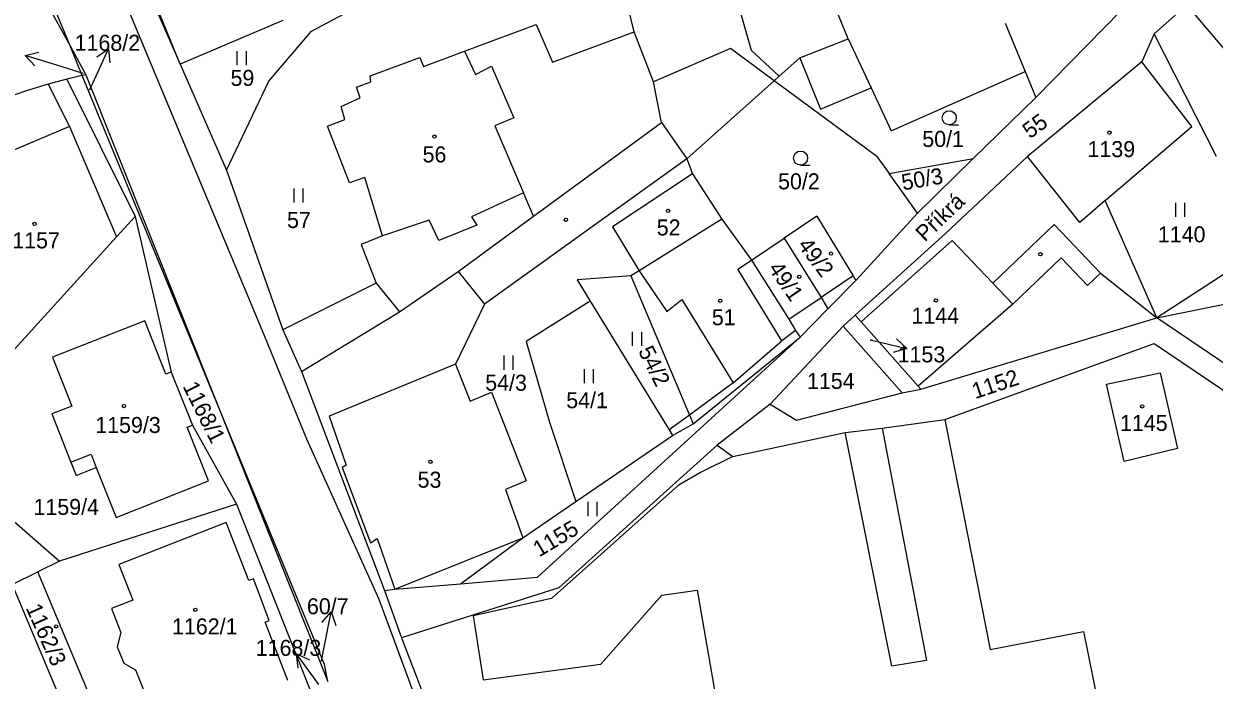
# Model space of a CAD drawing. Extents: x -670359 to -668019, y -978807 to -976674.
# Drawn here: x -670231.3 to -670104.9, y -977870.8 to -977801.1 of the extents above; entities that cross this region are included whole.
import ezdxf

# ---------------------------------------------------------------- set-up
doc = ezdxf.new("R2010")
doc.units = 0
for name, color, linetype in [('Hranice parcel', 7, 'Continuous'), ('Parcelní čísla', 7, 'Continuous'), ('Pop  PČ popisy', 7, 'Continuous'), ('Vnitřní kresba', 7, 'Continuous'), ('Značky budov', 7, 'Continuous'), ('Značky kultur', 7, 'Continuous')]:
    doc.layers.add(name, color=color, linetype=linetype)

msp = doc.modelspace()

# ---------------------------------------------------------------- linework, layer by layer
at = {"layer": 'Hranice parcel'}
for points in [[(-670183.39, -977889.81), (-670193.56, -977862.25), (-670201.26, -977845.22), (-670205.62, -977834.5), (-670231.98, -977771.32), (-670242.71, -977745.05), (-670249.53, -977728.04), (-670253.85, -977714.41), (-670254.54, -977710.9), (-670255.07, -977705.75), (-670255.17, -977699.87), (-670254.7, -977694.67), (-670252.82, -977684.15), (-670242.83, -977643.13)], [(-670241.06, -977776.57), (-670231.37, -977794.32), (-670228.95, -977798.75), (-670226.38, -977803.45)], [(-670160.77, -977780.44), (-670154.08, -977803.89)], [(-670224.46, -977783.08), (-670214.71, -977805.39)], [(-670166.5, -977801.96), (-670170.62, -977785.06)], [(-670143.78, -977802.68), (-670145.82, -977797.63)], [(-670226.38, -977803.45), (-670228.39, -977798.54)], [(-670200.75, -977801.88), (-670196.17, -977799.43)], [(-670123.86, -977808.92), (-670114.79, -977799.68)], [(-670107.82, -977799.09), (-670111.29, -977802.18)], [(-670203.78, -977800.74), (-670214.71, -977805.39)], [(-670184.52, -977803.99), (-670176.9, -977801.17)], [(-670176.9, -977801.17), (-670175.17, -977805.18)], [(-670205.27, -977807.21), (-670200.75, -977801.88)], [(-670175.17, -977805.18), (-670166.5, -977801.96)], [(-670164.46, -977807.25), (-670166.5, -977801.96)], [(-670148.92, -977804.72), (-670143.78, -977802.68)], [(-670111.29, -977802.18), (-670112.59, -977805.14)], [(-670104.66, -977815.19), (-670111.29, -977802.18)], [(-670226.38, -977803.45), (-670224.71, -977806.51)], [(-670225.09, -977806.6), (-670226.38, -977803.45)], [(-670188.86, -977805.64), (-670184.52, -977803.99)], [(-670154.08, -977803.89), (-670151.09, -977806.66)], [(-670214.71, -977805.39), (-670209.78, -977816.65)], [(-670194.54, -977806.64), (-670189.25, -977804.68)], [(-670189.25, -977804.68), (-670188.86, -977805.64)], [(-670148.92, -977804.72), (-670151.09, -977806.66)], [(-670148.92, -977804.72), (-670146.72, -977810.18)], [(-670112.59, -977805.14), (-670124.75, -977815.21)], [(-670107.3, -977812.02), (-670112.59, -977805.14)], [(-670225.09, -977806.6), (-670226.72, -977806.98)], [(-670224.71, -977806.51), (-670225.09, -977806.6)], [(-670211.12, -977840.59), (-670225.09, -977806.6)], [(-670224.71, -977806.51), (-670211.12, -977840.59)], [(-670194.47, -977807.28), (-670194.54, -977806.64)], [(-670151.63, -977807.14), (-670151.09, -977806.66)], [(-670139.21, -977812.47), (-670125, -977806.17)], [(-670125, -977806.17), (-670123.86, -977808.92)], [(-670228.72, -977807.52), (-670230.81, -977808.15)], [(-670226.72, -977806.98), (-670228.72, -977807.52)], [(-670228.72, -977807.52), (-670226.43, -977812.02)], [(-670226.72, -977806.98), (-670219.46, -977821.58)], [(-670209.78, -977816.65), (-670205.27, -977807.21)], [(-670195.99, -977807.83), (-670194.47, -977807.28)], [(-670195.6, -977808.95), (-670195.99, -977807.83)], [(-670163.61, -977811.58), (-670164.46, -977807.25)], [(-670160.92, -977815.43), (-670151.63, -977807.14)], [(-670140.75, -977815.18), (-670151.63, -977807.14)], [(-670146.72, -977810.18), (-670141.34, -977807.89)], [(-670141.34, -977807.89), (-670139.21, -977812.47)], [(-670230.81, -977808.15), (-670240.51, -977811.44)], [(-670197.61, -977809.9), (-670195.6, -977808.95)], [(-670123.86, -977808.92), (-670130.5, -977815.4)], [(-670197.22, -977811.26), (-670197.61, -977809.9)], [(-670199.06, -977811.97), (-670197.22, -977811.26)], [(-670177.17, -977821.54), (-670163.61, -977811.58)], [(-670163.61, -977811.58), (-670160.92, -977815.43)], [(-670226.43, -977812.02), (-670240, -977817.76)], [(-670196.71, -977817.98), (-670199.06, -977811.97)], [(-670116.48, -977819.88), (-670107.3, -977812.02)], [(-670160.92, -977815.43), (-670182.39, -977830.88)], [(-670160.92, -977815.43), (-670160.29, -977817.04)], [(-670140.75, -977815.18), (-670139.43, -977817.01)], [(-670139.43, -977817.01), (-670130.5, -977815.4)], [(-670136.43, -977821.2), (-670130.5, -977815.4)], [(-670124.75, -977815.21), (-670133.45, -977823.38)], [(-670119.19, -977822.2), (-670124.75, -977815.21)], [(-670209.78, -977816.65), (-670203.78, -977833.61)], [(-670195.1, -977817.44), (-670196.71, -977817.98)], [(-670193.23, -977823.61), (-670195.1, -977817.44)], [(-670160.29, -977817.04), (-670168.81, -977822.66)], [(-670160.29, -977817.04), (-670157.2, -977821.86)], [(-670136.43, -977821.2), (-670139.43, -977817.01)], [(-670178.23, -977819.07), (-670183.77, -977821.59)], [(-670177.17, -977821.54), (-670178.23, -977819.07)], [(-670116.48, -977819.88), (-670119.19, -977822.2)], [(-670111.02, -977832.34), (-670116.48, -977819.88)], [(-670219.46, -977821.58), (-670221.47, -977823.73)], [(-670219.46, -977821.58), (-670215.65, -977838.09)], [(-670185.17, -977827.42), (-670177.17, -977821.54)], [(-670183.77, -977821.59), (-670183.21, -977822.48)], [(-670147.12, -977821.53), (-670150.58, -977823.86)], [(-670147.12, -977821.53), (-670143.24, -977827.87)], [(-670142.95, -977828.35), (-670136.43, -977821.2)], [(-670188.25, -977821.96), (-670193.23, -977823.61)], [(-670187.23, -977824.13), (-670188.25, -977821.96)], [(-670183.21, -977822.48), (-670187.23, -977824.13)], [(-670168.81, -977822.66), (-670165.96, -977827.32)], [(-670157.2, -977821.86), (-670165.96, -977827.32)], [(-670157.2, -977821.86), (-670154.03, -977826.2)], [(-670221.47, -977823.73), (-670235.03, -977838.67)], [(-670154.03, -977826.2), (-670150.58, -977823.86)], [(-670150.58, -977823.86), (-670146.66, -977830.17)], [(-670133.45, -977823.38), (-670143.02, -977832.05)], [(-670099.93, -977825.14), (-670111.02, -977832.34)], [(-670154.03, -977826.2), (-670150.08, -977832.47)], [(-670191.4, -977831.7), (-670185.17, -977827.42)], [(-670166.85, -977827.87), (-670172.55, -977828.3)], [(-670165.96, -977827.32), (-670166.85, -977827.87)], [(-670166.85, -977827.87), (-670160.63, -977842.65)], [(-670143.24, -977827.87), (-670142.95, -977828.35)], [(-670172.55, -977828.3), (-670171.16, -977830.57)], [(-670142.95, -977828.35), (-670145.92, -977831.37)], [(-670171.16, -977830.57), (-670177.98, -977834.86)], [(-670171.16, -977830.57), (-670162.79, -977844.24)], [(-670146.66, -977830.17), (-670145.92, -977831.37)], [(-670111.02, -977832.34), (-670099.64, -977830.02)], [(-670201.81, -977838.02), (-670191.4, -977831.7)], [(-670182.39, -977830.88), (-670185.48, -977837.26)], [(-670148.89, -977834.39), (-670145.92, -977831.37)], [(-670218.46, -977832.65), (-670228.24, -977836.52)], [(-670216.21, -977838.32), (-670218.46, -977832.65)], [(-670150.08, -977832.47), (-670149.36, -977833.67)], [(-670143.02, -977832.05), (-670144.32, -977833.23)], [(-670143.02, -977832.05), (-670142.4, -977832.76)], [(-670142.4, -977832.76), (-670136.36, -977839.6)], [(-670136.08, -977839.92), (-670111.02, -977832.34)], [(-670087.45, -977848.3), (-670111.02, -977832.34)], [(-670203.78, -977833.61), (-670201.81, -977838.02)], [(-670176.76, -977859.87), (-670148.89, -977834.39)], [(-670160.24, -977843.59), (-670148.89, -977834.39)], [(-670144.32, -977833.23), (-670152.06, -977841.49)], [(-670149.36, -977833.67), (-670148.89, -977834.39)], [(-670144.32, -977833.23), (-670138.05, -977840.31)], [(-670177.98, -977834.86), (-670175.47, -977843.4), (-670172.69, -977851.85)], [(-670133.51, -977843.14), (-670111.28, -977835.06)], [(-670111.28, -977835.06), (-670086.58, -977851.74)], [(-670228.24, -977836.52), (-670226.19, -977841.7)], [(-670215.65, -977838.09), (-670216.21, -977838.32)], [(-670215.65, -977838.09), (-670213.37, -977843.72)], [(-670201.81, -977838.02), (-670193.02, -977861.28)], [(-670185.48, -977837.26), (-670183.91, -977841.19)], [(-670116.35, -977839.38), (-670110.67, -977838.18)], [(-670110.67, -977838.18), (-670108.8, -977846.19)], [(-670114.49, -977847.59), (-670116.35, -977839.38)], [(-670199.01, -977870.96), (-670199.39, -977869.14), (-670211.12, -977840.59)], [(-670211.12, -977840.59), (-670199.01, -977870.96)], [(-670183.91, -977841.19), (-670181.66, -977840.24)], [(-670181.66, -977840.24), (-670177.97, -977849.63)], [(-670149.27, -977843.19), (-670138.05, -977840.31)], [(-670138.05, -977840.31), (-670136.08, -977839.92)], [(-670136.36, -977839.6), (-670136.08, -977839.92)], [(-670226.19, -977841.7), (-670228.33, -977842.51)], [(-670152.06, -977841.49), (-670157.69, -977845.85)], [(-670152.06, -977841.49), (-670149.27, -977843.19)], [(-670228.33, -977842.51), (-670226.3, -977847.66)], [(-670160.63, -977842.65), (-670160.24, -977843.59)], [(-670140.16, -977844.05), (-670133.51, -977843.14)], [(-670133.51, -977843.14), (-670128.72, -977867.57)], [(-670213.94, -977843.94), (-670213.37, -977843.72)], [(-670211.69, -977849.63), (-670213.94, -977843.94)], [(-670213.37, -977843.72), (-670208.71, -977852.13)], [(-670162.79, -977844.24), (-670162.42, -977844.84)], [(-670162.42, -977844.84), (-670160.24, -977843.59)], [(-670156.02, -977847.06), (-670144.08, -977844.5)], [(-670144.08, -977844.5), (-670140.16, -977844.05)], [(-670172.69, -977851.85), (-670162.42, -977844.84)], [(-670157.69, -977845.85), (-670174.49, -977861)], [(-670157.69, -977845.85), (-670156.02, -977847.06)], [(-670108.8, -977846.19), (-670114.49, -977847.59)], [(-670226.3, -977847.66), (-670225.73, -977849.08)], [(-670225.73, -977849.08), (-670223.6, -977848.23)], [(-670223.6, -977848.23), (-670221.5, -977853.52)], [(-670221.5, -977853.52), (-670211.69, -977849.63)], [(-670177.97, -977849.63), (-670180.14, -977850.57)], [(-670180.14, -977850.57), (-670178.33, -977855.7)], [(-670208.71, -977852.13), (-670227.51, -977858.17)], [(-670208.71, -977852.13), (-670199.68, -977874.91)], [(-670178.33, -977855.7), (-670172.69, -977851.85)], [(-670234.05, -977852.48), (-670227.51, -977858.17)], [(-670209.8, -977854.06), (-670221.19, -977858.51)], [(-670207.39, -977860.24), (-670209.8, -977854.06)], [(-670184.95, -977860.58), (-670178.33, -977855.7)], [(-670227.51, -977858.17), (-670229.81, -977859.3)], [(-670232.52, -977860.64), (-670229.81, -977859.3)], [(-670223.55, -977874.27), (-670229.81, -977859.3)], [(-670221.19, -977858.51), (-670219.71, -977862.3)], [(-670232.52, -977860.64), (-670226.34, -977875.43)], [(-670206.92, -977860.06), (-670207.39, -977860.24)], [(-670205.23, -977864.49), (-670206.92, -977860.06)], [(-670191.89, -977861.13), (-670184.95, -977860.58)], [(-670174.49, -977861), (-670191.21, -977866.33)], [(-670184.95, -977860.58), (-670176.76, -977859.87)], [(-670193.02, -977861.28), (-670191.89, -977861.13)], [(-670193.02, -977861.28), (-670191.21, -977866.33)], [(-670219.71, -977862.3), (-670221.99, -977863.19)], [(-670221.99, -977863.19), (-670220.99, -977865.75)], [(-670205.66, -977864.66), (-670205.23, -977864.49)], [(-670203.25, -977870.84), (-670205.66, -977864.66)], [(-670220.99, -977865.75), (-670221.4, -977867.26)], [(-670128.72, -977867.57), (-670118.79, -977865.64)], [(-670118.79, -977865.64), (-670116.23, -977878.21)], [(-670221.4, -977867.26), (-670220.69, -977869.01)], [(-670191.21, -977866.33), (-670188.19, -977874.13)], [(-670220.69, -977869.01), (-670219.45, -977869.7)], [(-670219.45, -977869.7), (-670218.37, -977872.37)]]:
    msp.add_lwpolyline(points, dxfattribs=at)
at = {"layer": 'Parcelní čísla'}
for p, q in [((-670223.54, -977804.62), (-670222.32, -977803.75)), ((-670230.14, -977805.56), (-670231.16, -977804.46)), ((-670225, -977806.38), (-670227.34, -977805.65)), ((-670224.31, -977808.13), (-670223.97, -977807.39)), ((-670138.65, -977834.56), (-670137.56, -977835.6)), ((-670199.64, -977864.7), (-670198.65, -977863.57)), ((-670202.18, -977869.52), (-670202.34, -977868.02)), ((-670199.7, -977868.81), (-670199.43, -977867.49))]:
    msp.add_line(p, q, dxfattribs=at)
for points in [[(-670227.34, -977805.65), (-670231.16, -977804.46), (-670229.7, -977804.13)], [(-670223.97, -977807.39), (-670222.32, -977803.75), (-670222.17, -977805.24)], [(-670141.45, -977834.66), (-670137.56, -977835.6), (-670139, -977836.02)], [(-670199.43, -977867.49), (-670198.65, -977863.57), (-670198.17, -977864.99)], [(-670199.99, -977871.26), (-670202.34, -977868.02), (-670200.97, -977868.64)]]:
    msp.add_lwpolyline(points, dxfattribs=at)
at = {"layer": 'Vnitřní kresba'}
for points in [[(-670214.71, -977805.39), (-670222.8, -977785.49)], [(-670100.84, -977807.3), (-670107.82, -977799.09)], [(-670127.12, -977801.03), (-670125, -977806.17)], [(-670143.78, -977802.68), (-670141.34, -977807.89)], [(-670184.52, -977803.99), (-670183.34, -977806.48)], [(-670156.27, -977803.71), (-670164.46, -977807.25)], [(-670151.63, -977807.14), (-670156.27, -977803.71)], [(-670183.34, -977806.48), (-670181.65, -977805.61)], [(-670181.65, -977805.61), (-670179.29, -977811.07)], [(-670179.29, -977811.07), (-670181.3, -977811.93)], [(-670226.43, -977812.02), (-670221.47, -977823.73)], [(-670181.3, -977811.93), (-670178.23, -977819.07)], [(-670128.43, -977828.63), (-670121.91, -977822.42)], [(-670121.91, -977822.42), (-670116.98, -977827.6)], [(-670193.23, -977823.61), (-670195.47, -977824.55)], [(-670142.4, -977832.76), (-670132.73, -977824.11)], [(-670132.73, -977824.11), (-670128.43, -977828.63)], [(-670195.47, -977824.55), (-670193.9, -977828.64)], [(-670155.48, -977827.15), (-670154.03, -977826.2)], [(-670121.15, -977825.97), (-670126.3, -977830.87)], [(-670118.36, -977828.91), (-670121.15, -977825.97)], [(-670185.17, -977827.42), (-670182.39, -977830.88)], [(-670165.96, -977827.32), (-670163.03, -977831.66)], [(-670150.81, -977834.78), (-670155.48, -977827.15)], [(-670143.24, -977827.87), (-670146.66, -977830.17)], [(-670116.98, -977827.6), (-670118.36, -977828.91)], [(-670116.98, -977827.6), (-670111.02, -977832.34)], [(-670193.9, -977828.64), (-670203.78, -977833.61)], [(-670193.9, -977828.64), (-670191.4, -977831.7)], [(-670128.43, -977828.63), (-670126.3, -977830.87)], [(-670163.03, -977831.66), (-670161.42, -977830.39)], [(-670161.42, -977830.39), (-670155.97, -977839.22)], [(-670150.08, -977832.47), (-670146.66, -977830.17)], [(-670126.3, -977830.87), (-670136.36, -977839.6)], [(-670149.36, -977833.67), (-670150.81, -977834.78)], [(-670155.97, -977839.22), (-670150.81, -977834.78)], [(-670185.48, -977837.26), (-670198.88, -977842.76)], [(-670155.97, -977839.22), (-670160.63, -977842.65)], [(-670198.88, -977842.76), (-670197.08, -977847.97)], [(-670160.63, -977842.65), (-670162.79, -977844.24)], [(-670139.14, -977869.33), (-670144.08, -977844.5)], [(-670140.16, -977844.05), (-670135.45, -977868.72)], [(-670226.3, -977847.66), (-670224.16, -977846.81)], [(-670224.16, -977846.81), (-670223.6, -977848.23)], [(-670156.02, -977847.06), (-670159.4, -977848.72)], [(-670197.08, -977847.97), (-670197.48, -977848.21)], [(-670197.48, -977848.21), (-670194.5, -977856.23)], [(-670159.4, -977848.72), (-670161.81, -977850.14)], [(-670161.81, -977850.14), (-670175.26, -977862.12)], [(-670194.5, -977856.23), (-670193.78, -977855.75)], [(-670193.78, -977855.75), (-670191.89, -977861.13)], [(-670191.89, -977861.13), (-670178.33, -977855.7)], [(-670175.26, -977862.12), (-670183.59, -977863.98)], [(-670170.03, -977869.12), (-670163.57, -977861.8)], [(-670163.57, -977861.8), (-670159.81, -977861.27)], [(-670159.81, -977861.27), (-670157.73, -977873.28)], [(-670183.59, -977863.98), (-670182.52, -977870.79)], [(-670182.52, -977870.79), (-670170.03, -977869.12)], [(-670135.45, -977868.72), (-670139.14, -977869.33)]]:
    msp.add_lwpolyline(points, dxfattribs=at)
at = {"layer": 'Značky budov'}
for centre in [(-670187.7, -977813.07), (-670116.05, -977812.66), (-670162.89, -977820.98), (-670230.16, -977822.35), (-670145.6, -977825.5), (-670148.98, -977827.97), (-670157.36, -977830.51), (-670134.47, -977830.48), (-670220.67, -977841.71), (-670112.56, -977841.74), (-670188.12, -977847.61), (-670213.09, -977863.34), (-670227.86, -977865.1)]:
    msp.add_circle(centre, 0.175, dxfattribs=at)
at = {"layer": 'Značky kultur'}
for p, q in [((-670208.67, -977803.99), (-670208.67, -977805.49)), ((-670207.67, -977805.49), (-670207.67, -977803.99)), ((-670133.05, -977811.83), (-670132.05, -977811.83)), ((-670148.83, -977816.12), (-670147.83, -977816.12)), ((-670202.64, -977818.59), (-670202.64, -977820.09)), ((-670201.64, -977820.09), (-670201.64, -977818.59)), ((-670109.04, -977820.11), (-670109.04, -977821.61)), ((-670108.04, -977821.61), (-670108.04, -977820.11)), ((-670166.7, -977833.81), (-670166.7, -977835.31)), ((-670165.7, -977835.31), (-670165.7, -977833.81)), ((-670180.33, -977836.34), (-670180.33, -977837.84)), ((-670179.33, -977837.84), (-670179.33, -977836.34)), ((-670171.82, -977837.77), (-670171.82, -977839.27)), ((-670170.82, -977839.27), (-670170.82, -977837.77)), ((-670171.43, -977851.88), (-670171.43, -977853.38)), ((-670170.43, -977853.38), (-670170.43, -977851.88))]:
    msp.add_line(p, q, dxfattribs=at)
for centre, radius in [((-670133.05, -977811.08), 0.75), ((-670187.7, -977813.07), 0.175), ((-670116.05, -977812.66), 0.175), ((-670148.83, -977815.37), 0.75), ((-670173.75, -977821.91), 0.175), ((-670162.89, -977820.98), 0.175), ((-670230.16, -977822.35), 0.175), ((-670145.6, -977825.5), 0.175), ((-670123.37, -977825.58), 0.175), ((-670148.98, -977827.97), 0.175), ((-670157.36, -977830.51), 0.175), ((-670134.47, -977830.48), 0.175), ((-670220.67, -977841.71), 0.175), ((-670112.56, -977841.74), 0.175), ((-670188.12, -977847.61), 0.175), ((-670213.09, -977863.34), 0.175), ((-670227.86, -977865.1), 0.175)]:
    msp.add_circle(centre, radius, dxfattribs=at)

# ---------------------------------------------------------------- texts
at = {"layer": 'Parcelní čísla'}
for s, height, p in [('1168/2', 1.7, (-670225.9, -977803.97)), ('61/6', 0.1, (-670225.15, -977806.38)), ('59', 1.7, (-670209.35, -977807.7)), ('1168/2', 0.1, (-670224.54, -977808.13)), ('50/1', 1.7, (-670135.91, -977814.18)), ('56', 1.7, (-670188.96, -977815.82)), ('1139', 1.7, (-670118.37, -977815.26)), ('50/2', 1.7, (-670151.22, -977818.68)), ('57', 1.7, (-670203.35, -977822.79)), ('52', 1.7, (-670164.1, -977823.58)), ('1140', 1.7, (-670110.9, -977824.31)), ('1157', 1.7, (-670232.52, -977824.95)), ('51', 1.7, (-670158.25, -977833.11)), ('1144', 1.7, (-670137.06, -977832.94)), ('1153', 0.1, (-670141.45, -977834.66)), ('1153', 1.7, (-670138.53, -977837.06)), ('1154', 1.7, (-670148.15, -977839.88)), ('54/3', 1.7, (-670182.31, -977840.07)), ('54/1', 1.7, (-670173.71, -977841.93)), ('1159/3', 1.7, (-670223.71, -977844.56)), ('1145', 1.7, (-670114.92, -977844.34)), ('53', 1.7, (-670189.49, -977850.37)), ('1159/4', 1.7, (-670230.27, -977853.26)), ('60/7', 1.7, (-670201.24, -977863.81)), ('1162/1', 1.7, (-670215.56, -977865.95)), ('1168/3', 1.7, (-670206.67, -977868.23)), ('60/7', 0.1, (-670199.86, -977868.81))]:
    msp.add_text(s, height=height, dxfattribs=at).set_placement(p)
for s, rotation, p in [('55', 36.1796, (-670124.48, -977813.37)), ('50/3', 9.9274, (-670137.96, -977818.8)), ('49/2', 306.5911, (-670149.2, -977824.62)), ('49/1', 304.1436, (-670152.32, -977827.08)), ('54/2', 296.563, (-670166.11, -977835.84)), ('1152', 18.435, (-670130.29, -977840.97)), ('1168/1', 296.5651, (-670214.46, -977839.6)), ('1155', 30.8609, (-670176.58, -977857.78)), ('1162/3', 294.2744, (-670231.12, -977863.14))]:
    msp.add_text(s, height=1.7, rotation=rotation, dxfattribs=at).set_placement(p)
at = {"layer": 'Pop  PČ popisy'}
msp.add_text('Příkrá', height=1.7, rotation=43.8018, dxfattribs=at).set_placement((-670135.63, -977824.34))

doc.saveas('drawing.dxf')
